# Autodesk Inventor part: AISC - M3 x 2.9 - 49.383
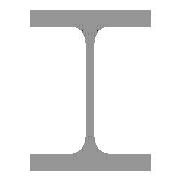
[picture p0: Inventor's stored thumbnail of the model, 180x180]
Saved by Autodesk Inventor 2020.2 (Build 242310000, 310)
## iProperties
_CCFamilyMember: 14
_CCFamilyDisplayName: ANSI M - M-Shape — Sizes in parentheses have been withdrawn
_FrameMemberDoc: Frame Member File
_Version: 15.0.0
_GetPNFromCC: 1
Created: 2019-01
Part Number: AISC - M3 x 2.9 - 49.383
Material: Steel, Mild
Description: M-Shape
Document SubType Name: Modeling
Standard: ANSI
Designer: thira
Standards Organization: ANSI
Language: en-US
Size Designation: M3 x 2.9
Categories: <MemberInstance><Categories><Category DisplayName="Structural Shapes" InternalName="089c4875-fa83-4c05-b084-43b9cc11f5ed" Mnemonic="GRDR"><CategoryParameter Dis
Stock Number: M3 x 2.9
Density: 7.85 g/cm^3
Appearance: Semi-Polished
G_L: 49.383 in
G_W: 2.250 in
G_H: 3.000 in
+2D74BDFD-F109-4072-BD78-AAB4B0D6E483+CUTDETAIL1: Miter 45.00 deg
+F925D24F-D68D-4F5E-A87D-887464E8C1D5+CUTDETAIL2: Miter 45.00 deg
IsCustomPart: 1
Author: thira
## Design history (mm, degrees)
node "Start Plane"
node "End Plane"
sketch "Sketch"
  geometry: L1 (-28.575, -38.1)-(-28.575, -34.798); L2 (-28.575, -34.798)-(-10.541, -34.798); L3 (-1.143, -25.4)-(-1.143, 0); L4 (-1.143, 0)-(0, 0); L5 (0, 0)-(0, -38.1); L6 (0, -38.1)-(-28.575, -38.1); L7 (-60, 0)-(80, 0); L8 (0, -60)-(0, 80); L9 (28.575, -38.1)-(28.575, -34.798); L10 (28.575, -34.798)-(10.541, -34.798); L11 (0, -38.1)-(28.575, -38.1); L12 (1.143, -25.4)-(1.143, 0); L13 (1.143, 0)-(0, 0); L14 (-28.575, 38.1)-(-28.575, 34.798); L15 (0, 38.1)-(-28.575, 38.1); L16 (0, 38.1)-(28.575, 38.1); L17 (28.575, 34.798)-(10.541, 34.798); L18 (-28.575, 34.798)-(-10.541, 34.798); L19 (1.143, 25.4)-(1.143, 0); L20 (-1.143, 25.4)-(-1.143, 0); L21 (28.575, 38.1)-(28.575, 34.798); L22 (0, 108)-(0, -88) reference; L23 (-88, 0)-(108, 0) reference; A1 r 9.398 centre (-10.541, 25.4) between (-1.143, 25.4) and (-10.541, 34.798); A2 r 9.398 centre (10.541, 25.4) between (10.541, 34.798) and (1.143, 25.4); A3 r 9.398 centre (10.541, -25.4) between (1.143, -25.4) and (10.541, -34.798); A4 r 9.398 centre (-10.541, -25.4) between (-10.541, -34.798) and (-1.143, -25.4); 4 further points
  constraints: 42 end point, 11 symmetric about line, 8 point on circle, 8 point on line, 8 tangent, 4 centre point, 4 collinear, 4 parallel, 3 equal radius, 1 perpendicular, 1 vertical, 13 other
  dimensions: "d1" = 38.1 vertical distance of L1.start L3.end (= 0.5 x G_H); "d2" = 3.302 distance between parallel lines of L2 L6 (= G_T1); "d3" = 28.575 distance from line of L5.end L1 (= 0.5 x G_W); "d4" = 1.143 distance between parallel lines of L5 L3 (= 0.5 x G_T); "d13" = 9.398 radius of A1 (= G_IR)
extrude "Body" new body sketch "Sketch" stored distance "d5" = 1254.32157 (= G_L); taper "d6" = 0 deg
node "Driven Length"
  sketch "Sketch4"
    geometry: L1 (0, 0)-(10, 0) reference
    constraints: 2 end point, 1 horizontal
  workplane "Work Plane3"
  sketch "Sketch5"
    geometry: L1 (-2, -27.161)-(12, -27.161) reference; L2 (-2, 1227.161)-(12, 1227.161) reference
    dimensions: "d15" = 1254.32157 distance between parallel lines of L1 L2 (derived)
workplane "Work Plane4"
split "Split1"
workplane "Work Plane5"
split "Split2"
body "Solid1"
other parameters: "G_W" = 57.15 [user parameter; used in 1 equation term], "G_H" = 76.2 [user parameter; used in 1 equation term], "G_T" = 2.286 [user parameter; used in 1 equation term], "G_T1" = 3.302 [user parameter; used in 1 equation term], "G_IR" = 9.398 [user parameter; used in 1 equation term], "G_L" = 1254.32157 (= d15) [user parameter; used in 1 equation term], "G_OFFSET_START" = 27.16079 [user parameter; used in 1 equation term], "G_OFFSET_END" = 27.16079 [user parameter; used in 1 equation term], "d11" = -27.16079 (= -G_OFFSET_START), "d12" = 1227.16079 (= G_OFFSET_END + B_L), "B_L" = 1200 [user parameter; used in 1 equation term], "d14" = 90 deg
